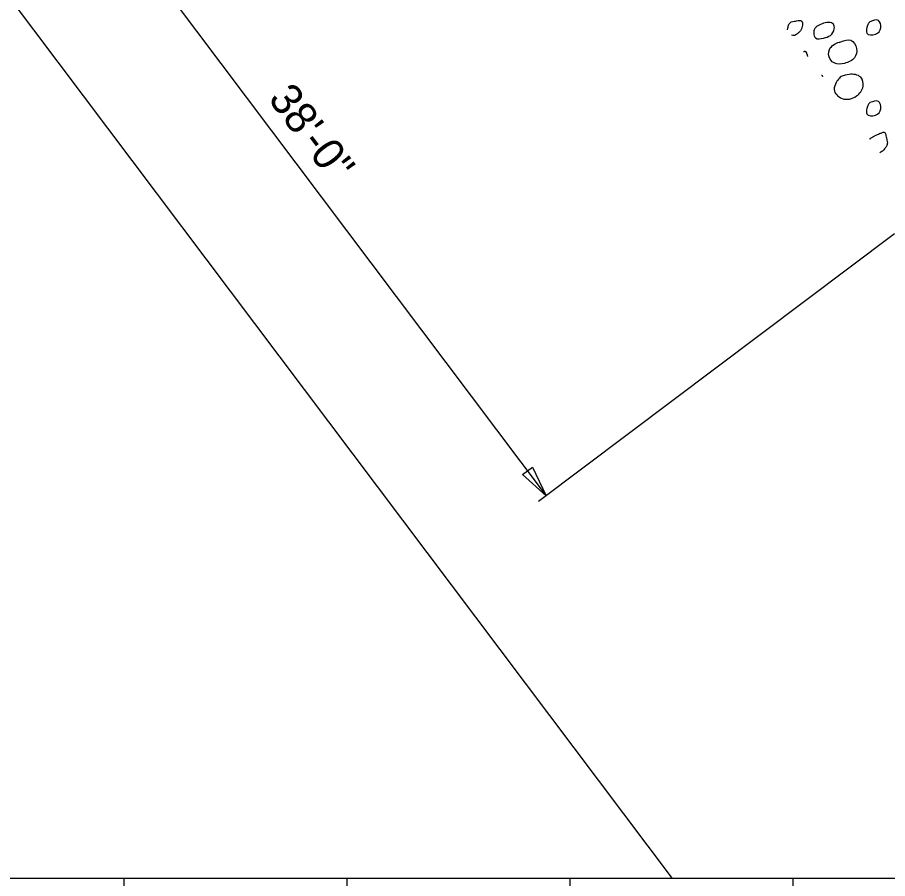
# Model space of a CAD drawing. Extents: x 0 to 1055, y 0 to 220.
# Drawn here: x 182.71 to 221.73, y 87.5 to 126.12 of the extents above; entities that cross this region are included whole.
import ezdxf

# ---------------------------------------------------------------- set-up
doc = ezdxf.new("R2010")
doc.units = 0
for name, color, linetype in [('BR_P_Brg_Centerline', 7, 'Continuous'), ('GE_P_Alignment_100_Cardinal_Points', 7, 'Continuous'), ('GE_P_Alignment_100_Distances', 7, 'Continuous'), ('GT_Project_Soil_Boring', 7, 'Continuous'), ('SC_Scratch1', 7, 'Continuous')]:
    doc.layers.add(name, color=color, linetype=linetype)

msp = doc.modelspace()

# ---------------------------------------------------------------- linework, layer by layer
at = {"layer": 'BR_P_Brg_Centerline'}
msp.add_line((317.5, 87.5), (17.5, 87.5), dxfattribs=at)
at = {"layer": 'GE_P_Alignment_100_Cardinal_Points'}
msp.add_line((212.094, 87.5), (116.145, 215), dxfattribs=at)
at = {"layer": 'GE_P_Alignment_100_Distances'}
for p, q in [((183.575, 135.033), (206.425, 104.671)), ((222.04, 116.422), (206.083, 104.413)), ((205.359, 105.621), (205.807, 105.958)), ((205.807, 105.958), (206.425, 104.671)), ((206.425, 104.671), (205.359, 105.621))]:
    msp.add_line(p, q, dxfattribs=at)
at = {"layer": 'GT_Project_Soil_Boring'}
for p, q in [((187.5, 17.5), (187.5, 87.5)), ((197.5, 17.5), (197.5, 87.5)), ((207.5, 17.5), (207.5, 87.5)), ((217.5, 17.5), (217.5, 87.5))]:
    msp.add_line(p, q, dxfattribs=at)
at = {"layer": 'SC_Scratch1'}
for points, degree in [([(217.245, 125.557), (217.249, 125.594), (217.258, 125.631), (217.268, 125.666), (217.283, 125.721), (217.29, 125.784), (217.326, 125.829), (217.353, 125.863), (217.379, 125.896), (217.406, 125.93)], 3), ([(217.406, 125.93), (217.533, 125.948), (217.661, 125.969), (217.788, 125.986), (217.901, 126.001), (217.928, 125.756), (217.892, 125.658), (217.852, 125.549), (217.754, 125.441), (217.652, 125.363), (217.596, 125.32), (217.506, 125.304), (217.426, 125.318)], 3), ([(217.969, 124.595), (218.057, 124.624), (218.111, 124.486), (218.144, 124.363)], 2), ([(218.766, 123.537), (218.786, 123.526), (218.803, 123.501), (218.816, 123.47)], 2), ([(221.146, 120.811), (221.263, 120.861), (221.381, 120.912), (221.498, 120.962), (221.619, 121.014), (221.679, 120.747), (221.705, 120.624), (221.734, 120.493), (221.7, 120.346), (221.594, 120.219), (221.53, 120.142), (221.46, 120.091), (221.386, 120.055)], 3), ([(220.928, 120.664), (220.938, 120.674), (220.95, 120.684), (220.962, 120.692), (221.023, 120.733), (221.085, 120.771), (221.146, 120.811)], 3)]:
    msp.add_open_spline(points, degree=degree, dxfattribs=at)
for points in [[(218.544, 125.713), (218.794, 125.838), (219.095, 125.896), (219.305, 125.815), (219.34, 125.612), (219.169, 125.315), (218.855, 125.195), (218.504, 125.201), (218.418, 125.417), (218.47, 125.617), (218.544, 125.713)], [(220.942, 125.93), (221.324, 125.986), (221.428, 125.658), (221.188, 125.363), (220.801, 125.42), (220.804, 125.666), (220.862, 125.829), (220.942, 125.93)], [(219.63, 125.024), (220.085, 125.1), (220.344, 124.72), (220.247, 124.313), (219.801, 124.061), (219.361, 124.063), (219.162, 124.242), (219.125, 124.687), (219.33, 124.9), (219.556, 125.008), (219.639, 125.026)], [(219.651, 123.473), (220.007, 123.566), (220.528, 123.434), (220.635, 123.032), (220.34, 122.597), (219.691, 122.486), (219.337, 122.884), (219.432, 123.203), (219.57, 123.395), (219.651, 123.473)], [(220.942, 122.3), (221.324, 122.355), (221.428, 122.027), (221.188, 121.733), (220.801, 121.79), (220.804, 122.035), (220.862, 122.199), (220.942, 122.3)]]:
    msp.add_spline(points, degree=3, dxfattribs=at)

# ---------------------------------------------------------------- texts
at = {"layer": 'GE_P_Alignment_100_Distances'}
msp.add_text('38\'-0"', height=1.41, rotation=306.963, dxfattribs=at).set_placement((193.919, 122.46))

doc.saveas('drawing.dxf')
